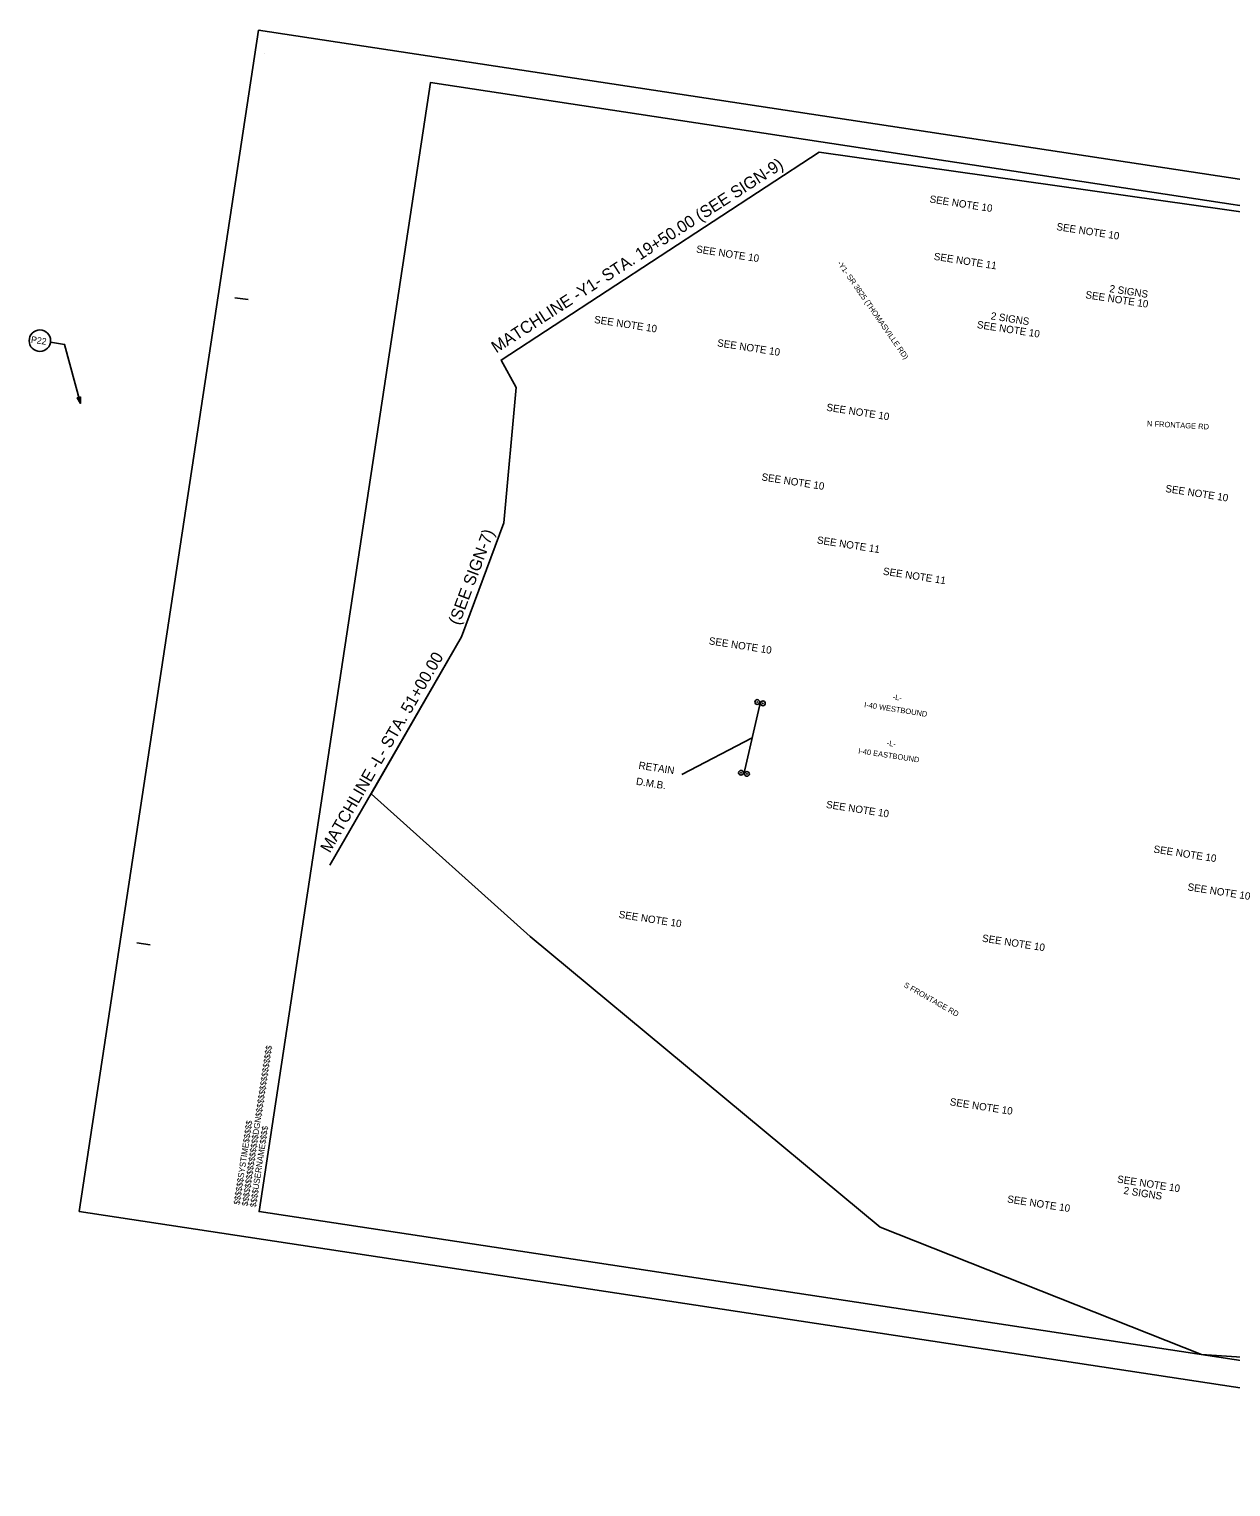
# Model space of a CAD drawing. Extents: x 1640181 to 1642275, y 841730 to 843072.
# Drawn here: x 1640181 to 1641287, y 841730 to 843072 of the extents above; entities that cross this region are included whole.
import ezdxf

# ---------------------------------------------------------------- set-up
doc = ezdxf.new("R2010")
doc.units = 0
for name, color, linetype in [('Default', 7, 'Continuous'), ('Level 14', 7, 'Continuous'), ('Level 2', 7, 'Continuous'), ('Level 22', 7, 'Continuous'), ('Level 3', 7, 'Continuous'), ('Level 38', 7, 'Continuous'), ('Level 41', 7, 'Continuous'), ('Level 5', 7, 'Continuous'), ('Level 6', 7, 'Continuous'), ('PLAN SHEETS', 7, 'Continuous')]:
    doc.layers.add(name, color=color, linetype=linetype)

msp = doc.modelspace()

# ---------------------------------------------------------------- linework, layer by layer
at = {"layer": 'Default'}
msp.add_lwpolyline([(1640200.2, 842783.9), (1640213.2, 842781.9), (1640227.8, 842727.6)], dxfattribs=at)
msp.add_lwpolyline([(1640227.8, 842733.6), (1640227.8, 842727.6), (1640224.8, 842732.8)], close=True, dxfattribs=at)
msp.add_circle((1640190.4, 842785.4), 9.89, dxfattribs=at)
at = {"layer": 'Level 14'}
msp.add_lwpolyline([(1640457.4, 842302.7), (1640578.7, 842512.8), (1640617.7, 842617.6), (1640629.1, 842742.4), (1640615, 842767.5), (1640908.1, 842958.8)], dxfattribs=at)
at = {"layer": 'Level 2'}
msp.add_lwpolyline([(1640226.7, 841983.7), (1641895.6, 841730.4), (1642060.7, 842817.9), (1640391.8, 843071.2)], close=True, dxfattribs=at)
msp.add_lwpolyline([(1640226.7, 841983.7), (1641895.6, 841730.4), (1642060.7, 842817.9), (1640391.8, 843071.2)], close=True, dxfattribs=at)
at = {"layer": 'Level 3'}
for p, q in [((1640392.7, 843072.2), (1640392.7, 843072.2)), ((1640396.9, 843050.2), (1640396.9, 843050.2)), ((1640551, 843022.8), (1640551, 843022.8)), ((1640369.9, 842825), (1640382.2, 842823.2)), ((1640279.7, 842231.2), (1640292.1, 842229.4)), ((1640392.3, 841983.8), (1640392.3, 841983.8)), ((1640392.3, 841983.8), (1640392.3, 841983.8)), ((1640392.3, 841983.8), (1640392.3, 841983.8)), ((1640392.3, 841983.8), (1640392.3, 841983.8)), ((1640392.3, 841983.8), (1640392.3, 841983.8)), ((1640392.3, 841983.8), (1640392.3, 841983.8)), ((1640392.3, 841983.8), (1640392.3, 841983.8)), ((1640392.3, 841983.8), (1640392.3, 841983.8))]:
    msp.add_line(p, q, dxfattribs=at)
msp.add_lwpolyline([(1642032.3, 842798), (1640550, 843023), (1640392.3, 841983.8), (1641874.6, 841758.9)], close=True, dxfattribs=at)
at = {"layer": 'Level 38'}
msp.add_line((1640846.2, 842419.8), (1640781.6, 842386.2), dxfattribs=at)
at = {"layer": 'Level 41'}
msp.add_line((1640853.8, 842453.1), (1640838.6, 842386.5), dxfattribs=at)
at = {"layer": 'Level 6'}
msp.add_lwpolyline([(1640495.4, 842368.4), (1640578.7, 842512.8), (1640617.7, 842617.6), (1640629.1, 842742.4), (1640615, 842767.5), (1640908.1, 842958.8), (1641847.5, 842826.1), (1641796.6, 842667.3), (1641752.4, 842181.8), (1641755.5, 842119.8), (1641647.9, 841984.8), (1641620.5, 841871.1), (1641550.3, 841881.8), (1641474.9, 841869.4), (1641375.1, 841879.2), (1641370.4, 841845), (1641260, 841852.1), (1640964.1, 841969.3), (1640641.8, 842236.9)], close=True, dxfattribs=at)
at = {"layer": 'PLAN SHEETS'}
for centre, radius in [((1640850.9, 842452.8), 2.18), ((1640850.9, 842452.8), 0.24), ((1640856.2, 842451.6), 2.18), ((1640856.2, 842451.6), 0.24), ((1640836, 842387.7), 2.18), ((1640836, 842387.7), 0.24), ((1640841.5, 842386.6), 2.18), ((1640841.5, 842386.6), 0.24)]:
    msp.add_circle(centre, radius, dxfattribs=at)

# ---------------------------------------------------------------- texts
at = {"layer": 'Default'}
for s, height, rotation, p in [('SEE NOTE 10', 6.771, 351.2099, (1641009.3, 842912.7)), ('SEE NOTE 10', 6.771, 351.2099, (1641126.1, 842887.3)), ('SEE NOTE 10', 6.771, 351.2099, (1640794.4, 842866.6)), ('SEE NOTE 11', 6.771, 351.2099, (1641013.2, 842859.9)), ('SEE NOTE 10', 6.771, 351.2099, (1641152.8, 842824.6)), ('2 SIGNS', 6.77, 351.2099, (1641174.9, 842830.2)), ('2 SIGNS', 6.77, 351.2099, (1641065.6, 842805.1)), ('SEE NOTE 10', 6.771, 351.2099, (1640700.4, 842801.8)), ('SEE NOTE 10', 6.771, 351.2099, (1641052.9, 842797.1)), ('P22', 6, 351.3708, (1640181.9, 842783.7)), ('SEE NOTE 10', 6.771, 351.2099, (1640813.7, 842780.3)), ('SEE NOTE 10', 6.771, 351.2099, (1640914.3, 842721)), ('SEE NOTE 10', 6.771, 351.2099, (1640854.5, 842656.9)), ('SEE NOTE 10', 6.771, 351.2099, (1641226.4, 842646.2)), ('SEE NOTE 11', 6.771, 351.2099, (1640905.6, 842598.8)), ('SEE NOTE 11', 6.771, 351.2099, (1640966.4, 842570.1)), ('SEE NOTE 10', 6.771, 351.2099, (1640806, 842506)), ('RETAIN', 6.77, 351.2099, (1640741.3, 842391.4)), ('D.M.B.', 6.77, 351.2099, (1640739, 842376.7)), ('SEE NOTE 10', 6.771, 351.2099, (1640914, 842355.4)), ('SEE NOTE 10', 6.771, 351.2099, (1641215.5, 842314.3)), ('SEE NOTE 10', 6.771, 351.2099, (1641246.8, 842279.5)), ('SEE NOTE 10', 6.771, 351.2099, (1640723, 842254.2)), ('SEE NOTE 10', 6.771, 351.2099, (1641057.6, 842232.3)), ('SEE NOTE 10', 6.771, 351.2099, (1641027.9, 842081.7)), ('SEE NOTE 10', 6.771, 351.2099, (1641182, 842010.5)), ('2 SIGNS', 6.77, 351.2099, (1641187.9, 842000.1)), ('SEE NOTE 10', 6.771, 351.2099, (1641080.8, 841992.2))]:
    msp.add_text(s, height=height, rotation=rotation, dxfattribs=at).set_placement(p)
at = {"layer": 'Level 22'}
for s, rotation, p in [('MATCHLINE -Y1- STA. 19+50.00 (SEE SIGN-9)', 32.8423, (1640610.6, 842773.6)), ('(SEE SIGN-7)', 69.3825, (1640576.5, 842522.9)), ('MATCHLINE -L- STA. 51+00.00', 59.9436, (1640457.4, 842313.2))]:
    msp.add_text(s, height=11, rotation=rotation, dxfattribs=at).set_placement(p)
at = {"layer": 'Level 3'}
for s, p in [('$$$$$$$$$$$$$$$$DGN$$$$$$$$$$$$$$$$', (1640381.8, 841988.5)), ('$$$$$$SYSTIME$$$$$', (1640374.3, 841989.7)), ('$$$$USERNAME$$$$', (1640389.3, 841987.4))]:
    msp.add_text(s, height=5.581, rotation=81.3707, dxfattribs=at).set_placement(p)
at = {"layer": 'Level 5'}
for s, rotation, p in [('-Y1- SR 3825 (THOMASVILLE RD)', 304.9178, (1640924.4, 842856.7)), ('N FRONTAGE RD', 356.9491, (1641209.7, 842706.7)), ('I-40 WESTBOUND', 351.1554, (1640949.1, 842448.1)), ('-L-', 351.1554, (1640975.4, 842455.2)), ('I-40 EASTBOUND', 351.4616, (1640943.7, 842405.5)), ('-L-', 351.4616, (1640969.9, 842412.7)), ('S FRONTAGE RD', 330.4543, (1640985.4, 842190.9))]:
    msp.add_text(s, height=5, rotation=rotation, dxfattribs=at).set_placement(p)

doc.saveas('drawing.dxf')
